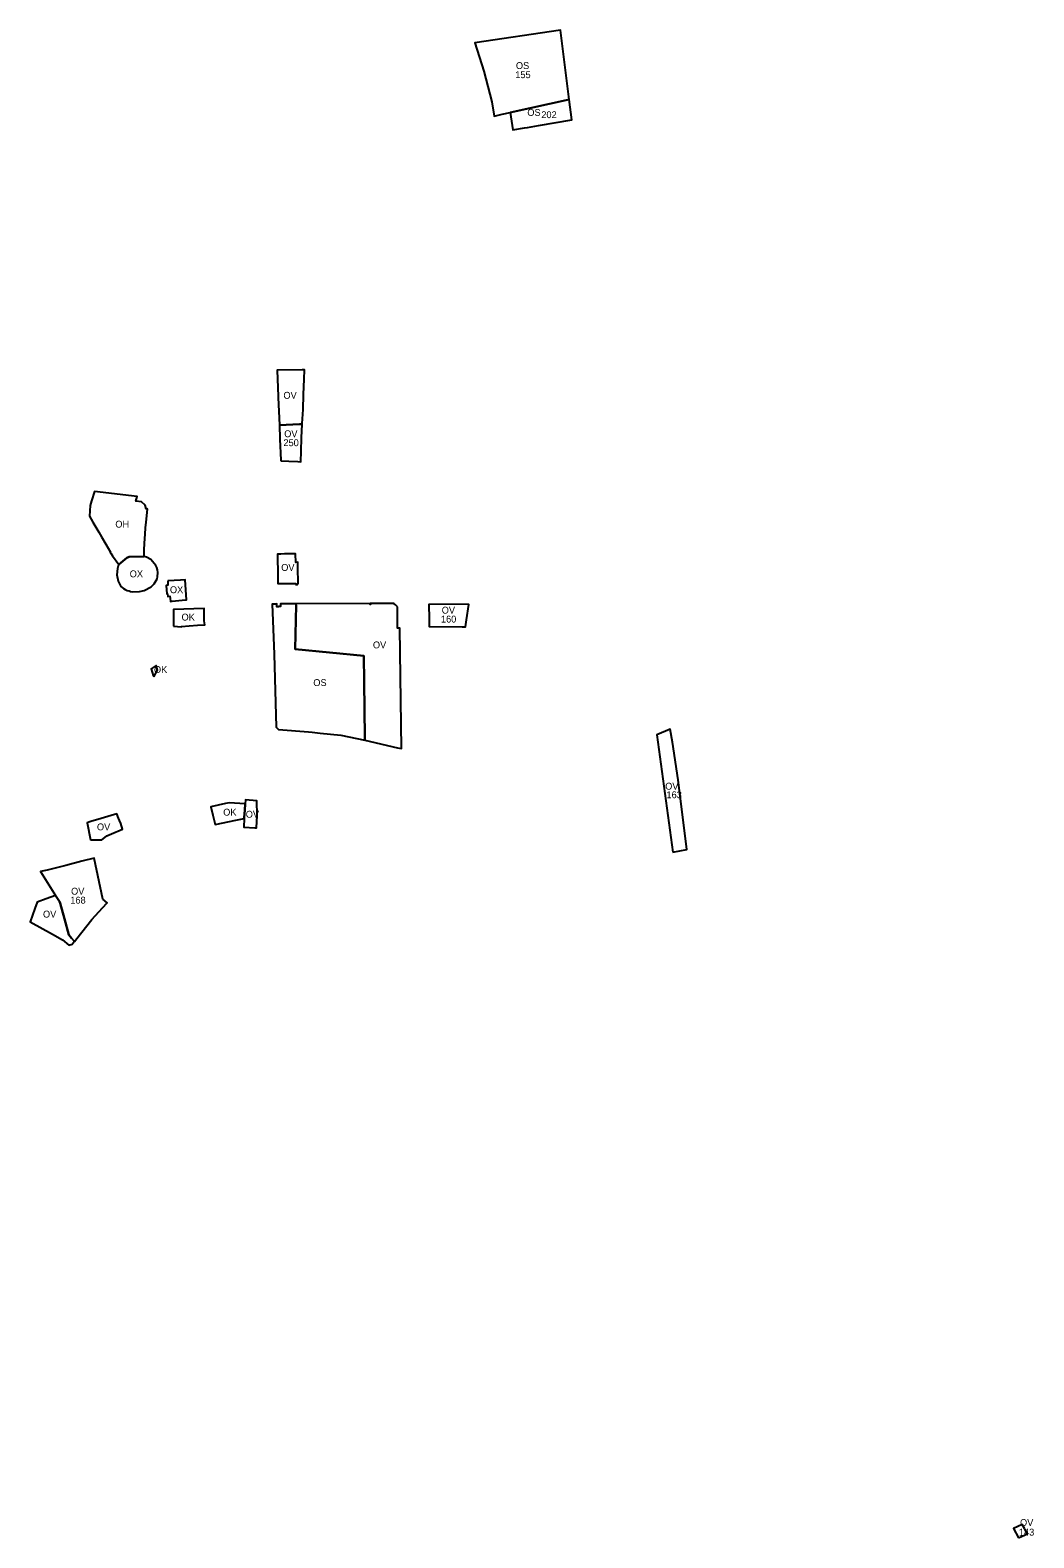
# Model space of a CAD drawing. Extents: x -521555 to -518220, y -1195001 to -1190632.
import ezdxf

# ---------------------------------------------------------------- set-up
doc = ezdxf.new("R2010")
doc.units = 0
for name, color, linetype in [('90140013', 7, 'Continuous'), ('90140023', 7, 'Continuous'), ('90210013', 7, 'Continuous'), ('90220013', 7, 'Continuous'), ('90290013', 7, 'Continuous'), ('90290023', 7, 'Continuous'), ('90300013', 7, 'Continuous'), ('ID_navrh', 7, 'Continuous')]:
    doc.layers.add(name, color=color, linetype=linetype)

msp = doc.modelspace()

# ---------------------------------------------------------------- linework, layer by layer
at = {"layer": '90140013'}
for points in [[(-519758.24, -1191204.87), (-519729.05, -1191203.74), (-519725.14, -1191203.59), (-519725.09, -1191202.63), (-519723.75, -1191182.31), (-519722.96, -1191160.4), (-519722.32, -1191138.09), (-519721.94, -1191124.81), (-519725.11, -1191124.72), (-519761.34, -1191125.25), (-519759.85, -1191163.64), (-519759.79, -1191165), (-519758.24, -1191204.87)], [(-519734.64, -1191436.32), (-519731.82, -1191436.25), (-519731.86, -1191434.94), (-519731.11, -1191434.94), (-519731.25, -1191411.74), (-519731.29, -1191404.25), (-519734.33, -1191404.3), (-519734.6, -1191391.84), (-519748.1, -1191392.08), (-519750.95, -1191392.13), (-519755.94, -1191392.22), (-519760.93, -1191392.31), (-519760.94, -1191392.31), (-519760.92, -1191394.34), (-519760.5, -1191422.78), (-519760.41, -1191429.18), (-519760.35, -1191433.14), (-519760.31, -1191435.14), (-519750.83, -1191435.08), (-519741.34, -1191435.03), (-519734.65, -1191434.99), (-519734.64, -1191436.32)], [(-519586.99, -1191468.38), (-519587.99, -1191467.28), (-519589.46, -1191465.93), (-519591.42, -1191464.38), (-519592.36, -1191464.04), (-519595.86, -1191463.83), (-519625.82, -1191463.94), (-519625.81, -1191465.57), (-519626.5, -1191465.57), (-519626.5, -1191463.94), (-519734.08, -1191464.3), (-519734.07, -1191466.44), (-519735.22, -1191530.23), (-519635.6, -1191540.05), (-519635.16, -1191577.68), (-519634.2, -1191658.3), (-519634.15, -1191662.4), (-519586.89, -1191673.37), (-519580.83, -1191674.78), (-519583.09, -1191499.99), (-519586.55, -1191499.99), (-519586.83, -1191468.84), (-519586.99, -1191468.38)], [(-519809.2, -1191776.23), (-519810.07, -1191788.65), (-519793.87, -1191789.77), (-519793.49, -1191789.8), (-519791.66, -1191789.94), (-519790.49, -1191771.67), (-519790.84, -1191750.42), (-519807.37, -1191749.03), (-519807.81, -1191754.83), (-519808.5, -1191763.95), (-519809.13, -1191774.84), (-519809.2, -1191776.23)], [(-520032.53, -1191806.97), (-520016.05, -1191807.34), (-520014.11, -1191805.56), (-520008.78, -1191801.57), (-520002.03, -1191798.56), (-519986.18, -1191791.5), (-519988.61, -1191783.49), (-519990.23, -1191779.13), (-519991.67, -1191775.9), (-519994.31, -1191769.26), (-520002.44, -1191771.82), (-520017.18, -1191776.24), (-520031.92, -1191780.65), (-520034.75, -1191781.51), (-520037.58, -1191782.36), (-520032.53, -1191806.97)], [(-520055.94, -1191954.58), (-520060.07, -1191949.85), (-520064.19, -1191945.12), (-520070.28, -1191922.07), (-520076.36, -1191899.02), (-520077.68, -1191896.92), (-520083.3, -1191887.96), (-520096.72, -1191892.86), (-520110.14, -1191897.75), (-520113.38, -1191906.91), (-520120.2, -1191926.19), (-520087.95, -1191943.96), (-520073.07, -1191952.16), (-520064.17, -1191960.26), (-520059.24, -1191958.73), (-520056.08, -1191954.75), (-520055.94, -1191954.58)]]:
    msp.add_lwpolyline(points, dxfattribs=at)
at = {"layer": '90140023'}
for points in [[(-519756.23, -1191256.68), (-519744.72, -1191257.28), (-519731.19, -1191257.99), (-519726.91, -1191258.21), (-519726.54, -1191242.87), (-519726.09, -1191223.67), (-519725.14, -1191203.59), (-519729.05, -1191203.74), (-519758.24, -1191204.87), (-519757.46, -1191224.85), (-519757.02, -1191236.26), (-519756.69, -1191244.83), (-519756.23, -1191256.68)], [(-519540.95, -1191464.89), (-519540.81, -1191486.75), (-519540.73, -1191497.56), (-519492.52, -1191498.07), (-519487.87, -1191498.12), (-519486.37, -1191487.58), (-519483.25, -1191465.69), (-519540.95, -1191464.89)], [(-519186.83, -1191825.25), (-519166.23, -1191821.08), (-519179.1, -1191720.15), (-519187.07, -1191665.36), (-519190.89, -1191646.39), (-519209.86, -1191654.59), (-519186.83, -1191825.25)], [(-520055.94, -1191954.58), (-520052.53, -1191950.29), (-520030.81, -1191922.99), (-520015.01, -1191905.83), (-520008.2, -1191898.59), (-520014.4, -1191893.4), (-520027.04, -1191833.79), (-520044.99, -1191838.35), (-520068.5, -1191844.29), (-520078.22, -1191846.75), (-520095.58, -1191851.22), (-520105.09, -1191853.21), (-520083.3, -1191887.96), (-520077.68, -1191896.92), (-520076.36, -1191899.02), (-520070.28, -1191922.07), (-520064.19, -1191945.12), (-520060.07, -1191949.85), (-520055.94, -1191954.58)], [(-518684.56, -1192820.7), (-518671.68, -1192814.76), (-518675.51, -1192807.93), (-518675.94, -1192807.15), (-518679.34, -1192801.09), (-518685.72, -1192804.11), (-518692.09, -1192807.13), (-518684.56, -1192820.7)]]:
    msp.add_lwpolyline(points, dxfattribs=at)
at = {"layer": '90210013'}
msp.add_lwpolyline([(-520030.97, -1191315.16), (-520033.05, -1191321.76), (-520034.19, -1191337.2), (-520029.08, -1191345.96), (-520026.17, -1191350.8), (-520020.3, -1191360.52), (-520016.46, -1191367.13), (-520010.34, -1191377.71), (-520003.6, -1191389.45), (-520003.86, -1191389.64), (-520003.01, -1191390.85), (-520000.38, -1191394.59), (-519991.42, -1191407.59), (-519979.79, -1191397.86), (-519976.17, -1191396.34), (-519954.76, -1191395.73), (-519954.6, -1191395.07), (-519954.39, -1191389.04), (-519954.59, -1191385.78), (-519953.49, -1191369.31), (-519953.12, -1191363.77), (-519952.46, -1191353.54), (-519951.87, -1191346.43), (-519951.44, -1191341.22), (-519949.88, -1191326.93), (-519950.9, -1191326.73), (-519951.55, -1191326.55), (-519952.92, -1191321.38), (-519958.31, -1191316.35), (-519966.71, -1191315.23), (-519964.93, -1191308.81), (-520026.6, -1191301.25), (-520030.97, -1191315.16)], dxfattribs=at)
at = {"layer": '90220013'}
for points in [[(-519911.87, -1191497.15), (-519900.4, -1191497.75), (-519900.37, -1191497.58), (-519889.18, -1191496.59), (-519877.19, -1191495.46), (-519866.65, -1191495.25), (-519867.28, -1191489.13), (-519867.51, -1191471.49), (-519912.09, -1191472.75), (-519911.87, -1191497.15)], [(-519940.69, -1191570.43), (-519935.12, -1191560.62), (-519937.21, -1191554.24), (-519944.39, -1191558.98), (-519941.33, -1191568.45), (-519940.69, -1191570.43)], [(-519809.2, -1191776.23), (-519809.13, -1191774.84), (-519808.5, -1191763.95), (-519807.81, -1191754.83), (-519830.94, -1191753.33), (-519836.61, -1191754.56), (-519857.83, -1191759.18), (-519854.69, -1191771.56), (-519851.31, -1191784.91), (-519821.34, -1191778.8), (-519809.2, -1191776.23)]]:
    msp.add_lwpolyline(points, dxfattribs=at)
at = {"layer": '90290013'}
msp.add_lwpolyline([(-519634.15, -1191662.4), (-519634.2, -1191658.3), (-519635.16, -1191577.68), (-519635.6, -1191540.05), (-519735.22, -1191530.23), (-519734.07, -1191466.44), (-519734.08, -1191464.3), (-519756.52, -1191464.38), (-519756.5, -1191468.24), (-519759.58, -1191468.17), (-519759.57, -1191468.66), (-519761.87, -1191468.64), (-519761.94, -1191464.39), (-519763.77, -1191464.94), (-519768.59, -1191464.89), (-519765.6, -1191537.51), (-519762.65, -1191643.76), (-519759.34, -1191647.09), (-519716.05, -1191650.55), (-519710.66, -1191650.95), (-519698.78, -1191652.19), (-519668.73, -1191655.24), (-519634.15, -1191662.4)], dxfattribs=at)
at = {"layer": '90290023'}
for points in [[(-519337.21, -1190732.05), (-519348.65, -1190643.36), (-519350.06, -1190631.54), (-519474.2, -1190649.71), (-519461.43, -1190691.22), (-519449.61, -1190735.43), (-519446.26, -1190756.2), (-519434.67, -1190753.64), (-519423.08, -1190751.07), (-519337.21, -1190732.05)], [(-519381.92, -1190770.01), (-519333.43, -1190761.83), (-519337.21, -1190732.05), (-519423.08, -1190751.07), (-519419.09, -1190776.27), (-519402.04, -1190773.36), (-519397.85, -1190772.66), (-519381.92, -1190770.01)]]:
    msp.add_lwpolyline(points, dxfattribs=at)
at = {"layer": '90300013'}
for points in [[(-519954.39, -1191445.09), (-519944.28, -1191439.79), (-519939.86, -1191435.3), (-519938.47, -1191433.25), (-519935.94, -1191428.27), (-519935.15, -1191425.43), (-519934.72, -1191419.07), (-519935.13, -1191415.1), (-519936.08, -1191411.87), (-519937.5, -1191408.96), (-519944.83, -1191400.03), (-519951.1, -1191396.7), (-519954.76, -1191395.73), (-519976.17, -1191396.34), (-519979.79, -1191397.86), (-519991.42, -1191407.59), (-519992.22, -1191409.33), (-519993.24, -1191413.37), (-519994.38, -1191422.52), (-519992.15, -1191431.52), (-519988.3, -1191439.28), (-519984.74, -1191442.4), (-519982.27, -1191443.78), (-519979.32, -1191444.93), (-519976.56, -1191445.88), (-519974.5, -1191446.39), (-519971.13, -1191446.91), (-519961.53, -1191446.75), (-519954.39, -1191445.09)], [(-519920.06, -1191431.33), (-519920.31, -1191437.6), (-519922.75, -1191437.85), (-519921.5, -1191449.97), (-519920.61, -1191449.84), (-519920.04, -1191453.76), (-519917.37, -1191453.48), (-519917.06, -1191456.51), (-519916.57, -1191461.19), (-519913.72, -1191460.84), (-519899.19, -1191459.03), (-519892.88, -1191458.5), (-519895.29, -1191429.8), (-519901.6, -1191430.33), (-519920.06, -1191431.33)]]:
    msp.add_lwpolyline(points, dxfattribs=at)

# ---------------------------------------------------------------- texts
at = {"layer": '90140013'}
for rotation, p in [(360, (-519752.34, -1191166.76)), (360, (-519755.57, -1191416.67)), (360, (-519622.37, -1191529.17)), (0, (-519807.06, -1191775.03)), (360, (-520023.17, -1191793.41)), (360, (-520101.54, -1191920.06))]:
    msp.add_text('OV', height=10, rotation=rotation, dxfattribs=at).set_placement(p)
at = {"layer": '90140023'}
for rotation, p in [(0, (-519751.23, -1191222.59)), (0, (-519522.43, -1191478.71)), (360, (-519197.9, -1191734.31)), (360, (-520060.74, -1191886.78)), (0, (-518682.5, -1192803.49))]:
    msp.add_text('OV', height=10, rotation=rotation, dxfattribs=at).set_placement(p)
at = {"layer": '90210013'}
msp.add_text('OH', height=10, rotation=0, dxfattribs=at).set_placement((-519996.49, -1191353.82))
at = {"layer": '90220013'}
for rotation, p in [(0, (-519900.35, -1191488.8)), (360, (-519940.36, -1191564.97)), (360, (-519839.82, -1191772.03))]:
    msp.add_text('OK', height=10, rotation=rotation, dxfattribs=at).set_placement(p)
at = {"layer": '90290013'}
msp.add_text('OS', height=10, rotation=0, dxfattribs=at).set_placement((-519708.95, -1191583.9))
at = {"layer": '90290023'}
for p in [(-519414.69, -1190688), (-519398.12, -1190756.05)]:
    msp.add_text('OS', height=10, rotation=360, dxfattribs=at).set_placement(p)
at = {"layer": '90300013'}
for rotation, p in [(0, (-519975.59, -1191425.96)), (360, (-519917.21, -1191449.09))]:
    msp.add_text('OX', height=10, rotation=rotation, dxfattribs=at).set_placement(p)
at = {"layer": 'ID_navrh'}
for s, rotation, p in [('155', 0, (-519415.62, -1190701.21)), ('202', 360, (-519377.8, -1190759.28)), ('250', 360, (-519752.37, -1191235.58)), ('160', 0, (-519523.57, -1191491.7)), ('163', 0, (-519195.99, -1191746.79)), ('168', 0, (-520061.88, -1191899.77)), ('143', 0, (-518684.16, -1192817.47))]:
    msp.add_text(s, height=10, rotation=rotation, dxfattribs=at).set_placement(p)

doc.saveas('drawing.dxf')
